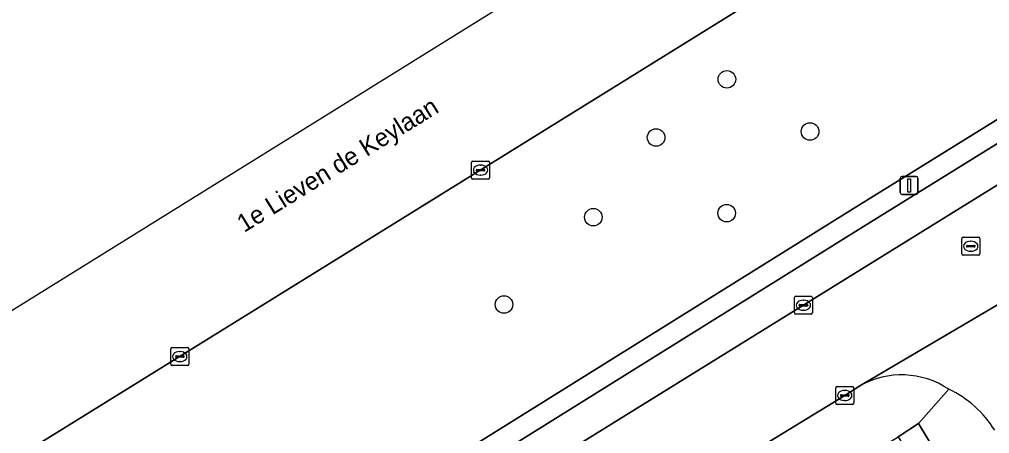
# Model space of a CAD drawing. Extents: x 160030 to 160839, y 385325 to 386450.
# Drawn here: x 160134.8 to 160188.9, y 386173.1 to 386196.2 of the extents above; entities that cross this region are included whole.
import ezdxf

# ---------------------------------------------------------------- set-up
doc = ezdxf.new("R2010")
doc.units = 0
for name, color, linetype in [('IMGEO_Berm_groen', 7, 'Continuous'), ('IMGEO_Boom', 7, 'Continuous'), ('IMGEO_Erf', 7, 'Continuous'), ('IMGEO_Kolk', 7, 'Continuous'), ('IMGEO_Lichtmast', 7, 'Continuous'), ('IMGEO_Openbare_ruimte_label', 7, 'Continuous'), ('IMGEO_Parkeervlak_open', 7, 'Continuous'), ('IMGEO_Rijbaan_lokaal_open', 7, 'Continuous'), ('IMGEO_Rijbaan_regionaal_gesloten', 7, 'Continuous'), ('IMGEO_Rioolput', 7, 'Continuous'), ('IMGEO_Voetpad_open', 7, 'Continuous')]:
    doc.layers.add(name, color=color, linetype=linetype)

msp = doc.modelspace()

# ---------------------------------------------------------------- linework, layer by layer
at = {"layer": 'IMGEO_Berm_groen'}
for points in [[(160234.469, 386218.598), (160277.33, 386245.172), (160280.701, 386245.111), (160288.622, 386250), (160297.811, 386255.671), (160290.722, 386267.055), (160290.073, 386268.104), (160268.911, 386254.994), (160262.546, 386251.044), (160260.864, 386250), (160234.899, 386233.885), (160206.043, 386216.043), (160153.804, 386183.592), (160128.715, 386168.047), (160086.922, 386142.123), (160078.853, 386137.104), (160078.685, 386136.999), (160079.791, 386135.22), (160079.109, 386134.797), (160079.894, 386133.531), (160076.58, 386131.475), (160075.795, 386132.741), (160071.15, 386129.885)], [(160077.328, 386121.006), (160081.949, 386123.902), (160132.017, 386154.864), (160181.265, 386185.59), (160234.469, 386218.598)]]:
    msp.add_lwpolyline(points, dxfattribs=at)
at = {"layer": 'IMGEO_Boom'}
for centre in [(160174.257, 386192.833), (160170.31, 386189.584), (160178.893, 386189.919), (160174.242, 386185.364), (160166.815, 386185.139), (160161.833, 386180.268)]:
    msp.add_circle(centre, 0.489, dxfattribs=at)
at = {"layer": 'IMGEO_Erf'}
msp.add_lwpolyline([(160188.598, 386167.569), (160184.94, 386173.628), (160183.8, 386172.886), (160187.504, 386166.893)], close=True, dxfattribs=at)
at = {"layer": 'IMGEO_Kolk'}
for p, q in [((160160.025, 386187.34), (160160.025, 386188.192)), ((160160.1, 386188.266), (160160.952, 386188.266)), ((160160.513, 386188.046), (160160.538, 386188.046)), ((160161.026, 386188.192), (160161.026, 386187.34)), ((160160.284, 386187.76), (160160.284, 386187.772)), ((160160.722, 386187.723), (160160.324, 386187.723)), ((160160.327, 386187.809), (160160.725, 386187.809)), ((160160.536, 386187.486), (160160.511, 386187.486)), ((160160.768, 386187.772), (160160.768, 386187.76)), ((160160.952, 386187.266), (160160.1, 386187.266)), ((160178.019, 386179.803), (160178.019, 386180.655)), ((160178.094, 386180.729), (160178.946, 386180.729)), ((160178.507, 386180.509), (160178.532, 386180.509)), ((160179.02, 386180.655), (160179.02, 386179.803)), ((160178.278, 386180.223), (160178.278, 386180.235)), ((160178.716, 386180.186), (160178.318, 386180.186)), ((160178.321, 386180.272), (160178.719, 386180.272)), ((160178.53, 386179.949), (160178.505, 386179.949)), ((160178.762, 386180.235), (160178.762, 386180.223)), ((160178.946, 386179.729), (160178.094, 386179.729)), ((160143.259, 386176.941), (160143.259, 386177.793)), ((160143.334, 386177.867), (160144.186, 386177.867)), ((160143.747, 386177.647), (160143.772, 386177.647)), ((160144.26, 386177.793), (160144.26, 386176.941)), ((160143.518, 386177.361), (160143.518, 386177.373)), ((160143.956, 386177.324), (160143.558, 386177.324)), ((160143.561, 386177.41), (160143.959, 386177.41)), ((160143.77, 386177.087), (160143.745, 386177.087)), ((160144.002, 386177.373), (160144.002, 386177.361)), ((160144.186, 386176.867), (160143.334, 386176.867)), ((160180.324, 386174.769), (160180.324, 386175.621)), ((160180.399, 386175.695), (160181.251, 386175.695)), ((160180.812, 386175.475), (160180.837, 386175.475)), ((160181.325, 386175.621), (160181.325, 386174.769)), ((160180.583, 386175.189), (160180.583, 386175.201)), ((160181.021, 386175.152), (160180.623, 386175.152)), ((160180.626, 386175.238), (160181.024, 386175.238)), ((160180.835, 386174.915), (160180.81, 386174.915)), ((160181.067, 386175.201), (160181.067, 386175.189)), ((160181.251, 386174.695), (160180.399, 386174.695))]:
    msp.add_line(p, q, dxfattribs=at)
for points in [[(160160.025, 386187.34), (160160.025, 386188.192)], [(160160.1, 386188.266), (160160.952, 386188.266)], [(160161.026, 386188.192), (160161.026, 386187.34)], [(160160.952, 386187.266), (160160.1, 386187.266)], [(160178.019, 386179.803), (160178.019, 386180.655)], [(160178.094, 386180.729), (160178.946, 386180.729)], [(160179.02, 386180.655), (160179.02, 386179.803)], [(160178.946, 386179.729), (160178.094, 386179.729)], [(160143.259, 386176.941), (160143.259, 386177.793)], [(160143.334, 386177.867), (160144.186, 386177.867)], [(160144.26, 386177.793), (160144.26, 386176.941)], [(160144.186, 386176.867), (160143.334, 386176.867)], [(160180.324, 386174.769), (160180.324, 386175.621)], [(160180.399, 386175.695), (160181.251, 386175.695)], [(160181.325, 386175.621), (160181.325, 386174.769)], [(160181.251, 386174.695), (160180.399, 386174.695)]]:
    msp.add_lwpolyline(points, dxfattribs=at)
for centre, radius, start, end in [((160160.102, 386188.19), 0.0765, 91.552, 178.448), ((160160.102, 386188.19), 0.0765, 91.552, 178.448), ((160160.95, 386188.19), 0.0765, 1.552, 88.448), ((160160.95, 386188.19), 0.0765, 1.552, 88.448), ((160160.102, 386187.342), 0.0765, 181.552, 268.448), ((160160.102, 386187.342), 0.0765, 181.552, 268.448), ((160160.324, 386187.769), 0.0403, 85.8775, 175.7526), ((160160.321, 386187.759), 0.0366, 178.938, 274.7102), ((160160.725, 386187.766), 0.043, 264.8664, 352.4533), ((160160.729, 386187.771), 0.0386, 1.7309, 96.639), ((160160.95, 386187.342), 0.0765, 271.552, 358.448), ((160160.95, 386187.342), 0.0765, 271.552, 358.448), ((160178.096, 386180.653), 0.0765, 91.552, 178.448), ((160178.096, 386180.653), 0.0765, 91.552, 178.448), ((160178.944, 386180.653), 0.0765, 1.552, 88.448), ((160178.944, 386180.653), 0.0765, 1.552, 88.448), ((160178.096, 386179.805), 0.0765, 181.552, 268.448), ((160178.096, 386179.805), 0.0765, 181.552, 268.448), ((160178.318, 386180.232), 0.0403, 85.8775, 175.7526), ((160178.315, 386180.222), 0.0366, 178.938, 274.7102), ((160178.719, 386180.229), 0.043, 264.8664, 352.4533), ((160178.723, 386180.234), 0.0386, 1.7309, 96.639), ((160178.944, 386179.805), 0.0765, 271.552, 358.448), ((160178.944, 386179.805), 0.0765, 271.552, 358.448), ((160143.336, 386177.791), 0.0765, 91.552, 178.448), ((160143.336, 386177.791), 0.0765, 91.552, 178.448), ((160144.184, 386177.791), 0.0765, 1.552, 88.448), ((160144.184, 386177.791), 0.0765, 1.552, 88.448), ((160143.558, 386177.37), 0.0403, 85.8775, 175.7526), ((160143.555, 386177.36), 0.0366, 178.938, 274.7102), ((160143.959, 386177.367), 0.043, 264.8664, 352.4533), ((160143.963, 386177.372), 0.0386, 1.7309, 96.639), ((160143.336, 386176.943), 0.0765, 181.552, 268.448), ((160143.336, 386176.943), 0.0765, 181.552, 268.448), ((160144.184, 386176.943), 0.0765, 271.552, 358.448), ((160144.184, 386176.943), 0.0765, 271.552, 358.448), ((160180.401, 386175.619), 0.0765, 91.552, 178.448), ((160180.401, 386175.619), 0.0765, 91.552, 178.448), ((160181.249, 386175.619), 0.0765, 1.552, 88.448), ((160181.249, 386175.619), 0.0765, 1.552, 88.448), ((160180.623, 386175.198), 0.0403, 85.8775, 175.7526), ((160180.62, 386175.188), 0.0366, 178.938, 274.7102), ((160181.024, 386175.195), 0.043, 264.8664, 352.4533), ((160181.028, 386175.2), 0.0386, 1.7309, 96.639), ((160180.401, 386174.771), 0.0765, 181.552, 268.448), ((160180.401, 386174.771), 0.0765, 181.552, 268.448), ((160181.249, 386174.771), 0.0765, 271.552, 358.448), ((160181.249, 386174.771), 0.0765, 271.552, 358.448)]:
    msp.add_arc(centre, radius, start, end, dxfattribs=at)
for centre, major_axis, ratio, start_param, end_param in [((160160.512, 386187.766), (-0.387, 0.002), 0.722429, 4.712389, 7.853982), ((160160.537, 386187.766), (-0.39, 0.002), 0.717154, 1.570796, 4.712389), ((160178.506, 386180.229), (-0.387, 0.002), 0.722429, 4.712389, 7.853982), ((160178.531, 386180.229), (-0.39, 0.002), 0.717154, 1.570796, 4.712389), ((160143.746, 386177.367), (-0.387, 0.002), 0.722429, 4.712389, 7.853982), ((160143.771, 386177.367), (-0.39, 0.002), 0.717154, 1.570796, 4.712389), ((160180.811, 386175.195), (-0.387, 0.002), 0.722429, 4.712389, 7.853982), ((160180.836, 386175.195), (-0.39, 0.002), 0.717154, 1.570796, 4.712389)]:
    msp.add_ellipse(centre, major_axis=major_axis, ratio=ratio, start_param=start_param, end_param=end_param, dxfattribs=at)
at = {"layer": 'IMGEO_Lichtmast'}
for p, q in [((160184.018, 386187.413), (160184.808, 386187.413)), ((160184.808, 386187.413), (160184.018, 386187.413)), ((160183.918, 386186.513), (160183.918, 386187.313)), ((160183.918, 386187.313), (160183.918, 386186.513)), ((160184.908, 386187.313), (160184.908, 386186.513)), ((160184.908, 386186.513), (160184.908, 386187.313)), ((160184.808, 386186.413), (160184.018, 386186.413)), ((160184.018, 386186.413), (160184.808, 386186.413))]:
    msp.add_line(p, q, dxfattribs=at)
msp.add_lwpolyline([(160184.338, 386187.288), (160184.488, 386187.288), (160184.488, 386186.538), (160184.338, 386186.538), (160184.338, 386187.288)], dxfattribs=at)
for centre, start, end in [((160184.018, 386187.313), 90, 180), ((160184.018, 386187.313), 90, 180), ((160184.808, 386187.313), 0, 90), ((160184.808, 386187.313), 360, 90), ((160184.018, 386186.513), 180, 270), ((160184.018, 386186.513), 180, 270), ((160184.808, 386186.513), 270, 0), ((160184.808, 386186.513), 270, 0)]:
    msp.add_arc(centre, 0.1, start, end, dxfattribs=at)
at = {"layer": 'IMGEO_Parkeervlak_open'}
for points in [[(160280.607, 386243.974), (160277.792, 386244.025), (160277.52, 386243.95), (160235.069, 386217.631), (160181.866, 386184.624), (160132.617, 386153.897), (160082.55, 386122.936), (160077.216, 386119.593)], [(160075.382, 386116.189), (160086.635, 386123.19), (160121.882, 386145.099), (160159.295, 386168.312), (160197, 386191.681)]]:
    msp.add_lwpolyline(points, dxfattribs=at)
at = {"layer": 'IMGEO_Rijbaan_lokaal_open'}
for points in [[(160195.535, 386184.31), (160204.903, 386190.137), (160202.023, 386194.798), (160197, 386191.681), (160159.295, 386168.312), (160121.882, 386145.099), (160086.635, 386123.19), (160075.382, 386116.189), (160074.167, 386115.433)], [(160180.827, 386175.198), (160181.672, 386175.731), (160193.669, 386182.792)], [(160193.669, 386182.792), (160181.672, 386175.731)], [(160119.733, 386137.358), (160126.429, 386141.473), (160146.817, 386154.266), (160156.724, 386160.411), (160165.557, 386165.852), (160180.827, 386175.198)]]:
    msp.add_lwpolyline(points, dxfattribs=at)
for centre, radius, start, end in [((160183.996, 386171.644), 4.701, 56.053, 119.6192), ((160184.041, 386170.067), 6.054, 31.743, 64.7798)]:
    msp.add_arc(centre, radius, start, end, dxfattribs=at)
at = {"layer": 'IMGEO_Rijbaan_regionaal_gesloten'}
for points in [[(160352.991, 386307.11), (160367.673, 386316.234), (160373.033, 386319.565), (160405.661, 386339.842), (160426.458, 386352.78), (160454.717, 386370.262), (160466.628, 386377.779), (160485.79, 386389.673), (160500, 386398.48), (160519.898, 386410.812), (160536.553, 386421.109), (160549.768, 386429.187), (160551.876, 386430.476), (160552.093, 386430.607), (160562.767, 386437.281), (160554.007, 386449.857), (160519.651, 386421.283), (160338.731, 386306.963), (160029.667, 386114.83)], [(160044.127, 386115.536), (160048.296, 386118.133), (160050.756, 386119.651), (160051.918, 386120.389), (160064.409, 386128.144), (160069.72, 386131.423), (160078.685, 386136.999), (160078.853, 386137.104), (160086.922, 386142.123), (160128.715, 386168.047), (160153.804, 386183.592), (160206.043, 386216.043), (160234.899, 386233.885), (160260.864, 386250), (160262.546, 386251.044), (160268.911, 386254.994), (160290.073, 386268.104), (160291.289, 386268.857), (160292.973, 386269.9), (160296.964, 386272.372), (160320.014, 386286.663), (160329.851, 386292.79), (160333.365, 386294.979)]]:
    msp.add_lwpolyline(points, dxfattribs=at)
at = {"layer": 'IMGEO_Rioolput'}
for p, q in [((160187.35, 386183.096), (160187.35, 386183.948)), ((160187.425, 386184.022), (160188.277, 386184.022)), ((160187.652, 386183.565), (160188.05, 386183.565)), ((160187.838, 386183.802), (160187.863, 386183.802)), ((160188.351, 386183.948), (160188.351, 386183.096)), ((160188.277, 386183.022), (160187.425, 386183.022)), ((160187.609, 386183.516), (160187.609, 386183.528)), ((160188.047, 386183.479), (160187.649, 386183.479)), ((160187.861, 386183.242), (160187.836, 386183.242)), ((160188.093, 386183.528), (160188.093, 386183.516))]:
    msp.add_line(p, q, dxfattribs=at)
for points in [[(160187.35, 386183.096), (160187.35, 386183.948)], [(160187.425, 386184.022), (160188.277, 386184.022)], [(160188.351, 386183.948), (160188.351, 386183.096)], [(160188.277, 386183.022), (160187.425, 386183.022)]]:
    msp.add_lwpolyline(points, dxfattribs=at)
for centre, radius, start, end in [((160187.427, 386183.946), 0.0765, 91.552, 178.448), ((160187.427, 386183.946), 0.0765, 91.552, 178.448), ((160187.649, 386183.525), 0.0403, 85.8775, 175.7526), ((160188.054, 386183.527), 0.0386, 1.7309, 96.639), ((160188.275, 386183.946), 0.0765, 1.552, 88.448), ((160188.275, 386183.946), 0.0765, 1.552, 88.448), ((160187.427, 386183.098), 0.0765, 181.552, 268.448), ((160187.427, 386183.098), 0.0765, 181.552, 268.448), ((160187.646, 386183.515), 0.0366, 178.938, 274.7102), ((160188.05, 386183.522), 0.043, 264.8664, 352.4533), ((160188.275, 386183.098), 0.0765, 271.552, 358.448), ((160188.275, 386183.098), 0.0765, 271.552, 358.448)]:
    msp.add_arc(centre, radius, start, end, dxfattribs=at)
for centre, major_axis, ratio, start_param, end_param in [((160187.837, 386183.522), (-0.387, 0.002), 0.722429, 4.712389, 7.853982), ((160187.862, 386183.522), (-0.39, 0.002), 0.717154, 1.570796, 4.712389)]:
    msp.add_ellipse(centre, major_axis=major_axis, ratio=ratio, start_param=start_param, end_param=end_param, dxfattribs=at)
at = {"layer": 'IMGEO_Voetpad_open'}
for points in [[(160341.022, 386282.591), (160315.759, 386266.812), (160299.088, 386256.53), (160291.945, 386267.798), (160291.289, 386268.857), (160290.073, 386268.104), (160290.722, 386267.055), (160297.811, 386255.671), (160288.622, 386250), (160280.701, 386245.111), (160277.33, 386245.172), (160234.469, 386218.598), (160181.265, 386185.59), (160132.017, 386154.864), (160081.949, 386123.902), (160077.328, 386121.006)], [(160077.216, 386119.593), (160082.55, 386122.936), (160132.617, 386153.897), (160181.866, 386184.624), (160235.069, 386217.631), (160277.52, 386243.95), (160277.792, 386244.025), (160280.607, 386243.974)], [(160116.22, 386131.592), (160118.647, 386133.098), (160147.737, 386151.111), (160150.164, 386152.647), (160157.455, 386157.125), (160160.061, 386158.73), (160172.13, 386166.269), (160173.339, 386167.024), (160173.586, 386166.593), (160173.67, 386166.644), (160176.044, 386168.092), (160183.8, 386172.886), (160184.94, 386173.628), (160186.621, 386175.544)], [(160181.672, 386175.731), (160180.827, 386175.198), (160165.557, 386165.852), (160156.724, 386160.411), (160146.817, 386154.266), (160126.429, 386141.473), (160119.733, 386137.358)], [(160186.621, 386175.544), (160184.94, 386173.628), (160188.598, 386167.569), (160190.069, 386165.189), (160197.128, 386153.726), (160198.561, 386151.408), (160205.629, 386140.047), (160207.096, 386137.673), (160214.1, 386126.287), (160215.559, 386123.926), (160219.724, 386117.207)]]:
    msp.add_lwpolyline(points, dxfattribs=at)
for centre, radius, start, end in [((160183.996, 386171.644), 4.701, 56.053, 119.6192), ((160184.041, 386170.067), 6.054, 31.743, 64.7798)]:
    msp.add_arc(centre, radius, start, end, dxfattribs=at)

# ---------------------------------------------------------------- texts
at = {"layer": 'IMGEO_Openbare_ruimte_label'}
msp.add_text('1e Lieven de Keylaan', height=1, rotation=31.7989, dxfattribs=at).set_placement((160147.347, 386184.257))

doc.saveas('drawing.dxf')
